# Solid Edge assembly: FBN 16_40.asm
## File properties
Title: Zylinder
Author: bmolnar
Template: iso assembly.asm
Last saved by: bmolnar
Revision: 21
Application: Solid Edge
Username: bmolnar
Dokumentum tartalom típus: 1
Document Number: FBN 16/40
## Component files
Kolbenstange.par
Profilrohr.par
Kit_1.par
Kit_2.par
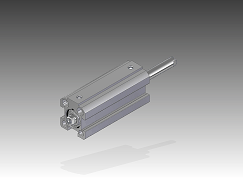
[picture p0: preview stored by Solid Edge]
